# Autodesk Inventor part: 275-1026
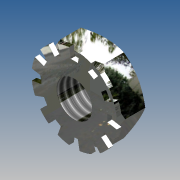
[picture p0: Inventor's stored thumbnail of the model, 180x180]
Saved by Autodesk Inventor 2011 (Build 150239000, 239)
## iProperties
Shininess: 70.0
Length Units: 11272
Angle Units: 11279
Time Units: 11290
Mass Units: 11286
Length Display Precision: 4
Angle Display Precision: 2
Compacted: True
Company: Autodesk Inc.
Created: 2010-06
Part Number: 275-1026
Material: Stainless Steel, 440C
Description: Keps Nut #8-32
Document SubType Name: Modeling
Designer: Autodesk Inc.
Density: 7.75 g/cm^3
Catalog Web Link: http://www.vexrobotics.com/nuts-8-32.html
Vendor: Innovation First, Inc.
Density: 7.75
Volumn: 0.07820028819372563
Area: 1.577785810948415
PropertySet Name: Model Information
Control State: 0
Master: False
Checked Out: False
Author: Autodesk Inc.
Title: VEX Robotics Kit of Parts
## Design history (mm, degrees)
sketch "Sketch8"
  geometry: L1 (-0.611, 4.984)-(-0.417, 3.881); L2 (-0.417, 3.881)-(0.417, 3.881); L3 (0.417, 3.881)-(0.611, 4.984); C1 r 2.083 at (0, 0) reference; C2 r 5.021 at (0, 0) reference; A1 r 5.021 centre (0, 0) between (0.611, 4.984) and (-0.611, 4.984)
  constraints: 6 end point, 2 concentric, 2 point on circle, 1 centre point, 1 equal length, 1 horizontal
  dimensions: "d21" = 100 deg angle of L2 L1; "d22" = 100 deg angle of L2 L3 (= d21); "d23" = 3.88112 vertical distance of C1.centre L2.end (= 0.444444 x Flats); "d24" = 0.83312 distance of L1.end L2.end (= 0.2 x HoleDiam)
extrude "Extrusion6" cut sketch "Sketch8" distance "d25" = 0.54555 (= d19); taper "d26" = 0 deg
pattern_circular "Circular Pattern1" dims angle "d29" = 360 deg
sketch "Sketch4"
  geometry: L1 (0, 3.137)-(4.366, 3.137) reference; L2 (4.366, 3.137)-(8.733, 0.616); L3 (0, 0)-(0, 3.137) reference; L4 (4.366, 3.137)-(8.733, 3.137); L5 (8.733, 0.616)-(8.733, 3.137)
  constraints: 6 end point, 2 perpendicular
  dimensions: "d6" = 8.73252 distance from line of L3 L2.end (= Flats); "d7" = 30 deg angle of L4 L2
revolve "Revolution1" stored, may be unused: angle "d8" = 90 deg
workplane "Work Plane1"
mirror "Mirror1"
sketch "Sketch5"
  geometry: C1 r 2.083 at (0, 0); A1 r 4.366 centre (0, 0) between (0, 4.366) and (-3.781, 2.183) reference
  constraints: 1 centre point, 1 coincident
  dimensions: "HoleDiam" = 4.1656 diameter of C1
extrude "Extrusion3" cut sketch "Sketch5" stored distance "d11" = 6.35; taper "d12" = 0 deg
thread "Thread1" dims "d13" = 25.4, "d14" = 0
sketch "Sketch7"
  geometry: C1 r 2.083 at (0, 0) reference; C2 r 5.021 at (0, 0); A1 r 4.366 centre (0, 0) between (0, 4.366) and (-3.781, 2.183) reference
  constraints: 1 centre point, 1 coincident
  dimensions: "d18" = 10.0424 diameter of C2 (= 1.15 x Flats)
extrude "Extrusion5" join sketch "Sketch7" distance "d19" = 0.54555 (= 0.173913 x Height); taper "d20" = 0 deg
body "Solid1"
sketch "Sketch2"
  geometry: L1 (-2.521, 4.366)-(2.521, 4.366); L2 (2.521, 4.366)-(5.042, 0); L3 (5.042, 0)-(2.521, -4.366); L4 (2.521, -4.366)-(-2.521, -4.366); L5 (-2.521, -4.366)-(-5.042, 0); L6 (-5.042, 0)-(-2.521, 4.366); L7 (0, 14.665)-(0, -10.999) reference; L8 (-10.999, 0)-(14.665, 0) reference; A1 r 5.042 centre (0, 0) between (-2.521, 4.366) and (2.521, 4.366); 1 further point
  constraints: 12 end point, 6 point on circle, 3 equal length, 2 point on line, 1 centre point, 1 coincident, 1 parallel, 1 other
  dimensions: "Flats" = 8.73252 distance between parallel lines of L2 L5
extrude "Extrusion2" new body sketch "Sketch2" taper "d4" = 0 deg; distance "Height" = 3.1369
other parameters: "Mirror_Plane" = -1.56845 (= -0.5 x Height)
